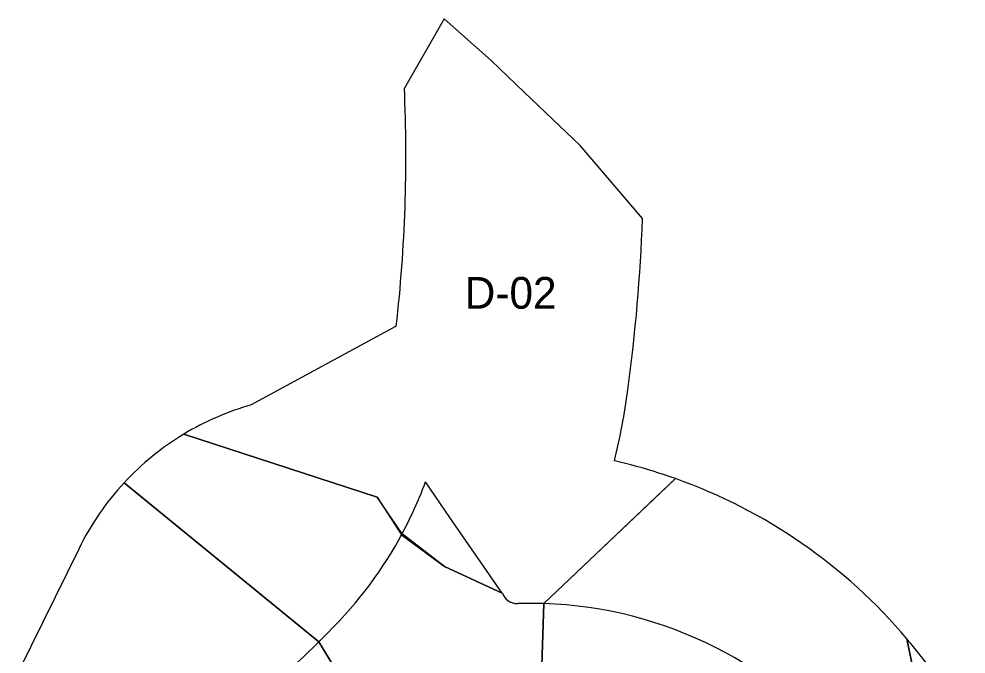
# Model space of a CAD drawing. Extents: x 5196716 to 5200291, y 3709146 to 3713154.
# Drawn here: x 5196804.5 to 5196983.8, y 3709425.2 to 3709545.4 of the extents above; entities that cross this region are included whole.
import ezdxf

# ---------------------------------------------------------------- set-up
doc = ezdxf.new("R2010")
doc.units = 0
for name, color, linetype in [('dsnTextNote', 7, 'Continuous'), ('Level 1', 7, 'Continuous'), ('Level 2', 7, 'Continuous')]:
    doc.layers.add(name, color=color, linetype=linetype)

msp = doc.modelspace()

# ---------------------------------------------------------------- linework, layer by layer
at = {"layer": 'Level 1'}
for p, q in [((5196884.99, 3709545.38), (5196877.49, 3709532.31)), ((5196922.56, 3709507.59), (5196910.77, 3709521.46)), ((5196875.95, 3709487.24), (5196848.49, 3709472.33)), ((5196920.33, 3709460.99), (5196917.26, 3709461.79)), ((5196903.91, 3709434.75), (5196928.82, 3709458.39)), ((5196928.82, 3709458.39), (5196927.19, 3709456.84)), ((5196824.43, 3709457.61), (5196838.6, 3709446.05)), ((5196927.19, 3709456.84), (5196922.24, 3709452.14)), ((5196922.24, 3709452.14), (5196903.91, 3709434.75)), ((5196922.24, 3709452.14), (5196903.91, 3709434.75)), ((5196838.6, 3709446.05), (5196861.31, 3709427.51)), ((5196815.9, 3709445.18), (5196804.52, 3709421.99)), ((5196903.91, 3709434.75), (5196902.74, 3709399.27)), ((5196902.74, 3709399.27), (5196903.91, 3709434.75)), ((5196903.91, 3709434.75), (5196902.74, 3709399.27)), ((5196874.95, 3709404.96), (5196861.31, 3709427.51)), ((5196861.31, 3709427.51), (5196874.95, 3709404.96)), ((5196993.25, 3709402.11), (5196974.62, 3709425.62))]:
    msp.add_line(p, q, dxfattribs=at)
for points in [[(5196910.77, 3709521.46), (5196900.25, 3709531.49), (5196893.9, 3709537.51), (5196884.99, 3709545.38)], [(5196877.1, 3709447.93), (5196872.32, 3709454.91), (5196835.71, 3709466.79)], [(5196835.71, 3709466.79), (5196872.32, 3709454.91), (5196876.97, 3709447.75)], [(5196928.82, 3709458.39), (5196927.19, 3709456.84), (5196922.24, 3709452.14)], [(5196861.31, 3709427.51), (5196838.6, 3709446.05), (5196824.43, 3709457.61)], [(5196876.97, 3709447.75), (5196885.1, 3709441.76), (5196896.03, 3709436.71)], [(5196896.03, 3709436.71), (5196885.1, 3709441.76), (5196877.1, 3709447.93)], [(5196898.85, 3709434.75), (5196898.94, 3709434.75)], [(5196972.61, 3709428.08), (5196978.06, 3709401.82), (5196980.89, 3709391.88), (5196981.68, 3709390)], [(5196981.68, 3709390), (5196980.89, 3709391.88), (5196978.06, 3709401.82), (5196972.61, 3709428.08)]]:
    msp.add_lwpolyline(points, dxfattribs=at)
for centre, radius, start, end in [((5196592.28, 3709519.5), 285.5, 353.512, 2.5728), ((5196592.28, 3709519.5), 330.5, 352.292, 357.936), ((5196790.47, 3709492.67), 130.5, 346.3114, 352.292), ((5196862.58, 3709422.27), 52, 105.7213, 121.1144), ((5196862.58, 3709422.27), 52, 121.1144, 137.1886), ((5196894.68, 3709362.27), 102, 70.4438, 75.4333), ((5196894.68, 3709362.27), 102, 40.1801, 70.4438), ((5196862.58, 3709422.27), 52, 137.1886, 153.8681), ((5196898.85, 3709437.75), 3, 200.28, 271.7877), ((5196898.85, 3709437.75), 3, 200.28, 270), ((5196901.36, 3709357.29), 77.5, 88.1128, 91.7877), ((5196901.36, 3709357.29), 77.5, 88.1128, 91.7877), ((5196894.68, 3709362.27), 102, 38.3928, 40.1801)]:
    msp.add_arc(centre, radius, start, end, dxfattribs=at)
at = {"layer": 'Level 2'}
for p, q in [((5196902.74, 3709399.27), (5196903.91, 3709434.75)), ((5196903.91, 3709434.75), (5196902.74, 3709399.27)), ((5196861.31, 3709427.51), (5196874.95, 3709404.96)), ((5196874.95, 3709404.96), (5196861.31, 3709427.51))]:
    msp.add_line(p, q, dxfattribs=at)
msp.add_lwpolyline([(5196896.03, 3709436.71), (5196886.07, 3709451.03), (5196881.5, 3709457.76)], dxfattribs=at)
for centre, radius, start, end in [((5196790.47, 3709492.67), 97.5, 335.3542, 339.0156), ((5196810.92, 3709483.29), 75, 317.5889, 335.3542), ((5196898.85, 3709437.75), 3, 200.28, 270), ((5196898.85, 3709437.75), 3, 270, 271.7877), ((5196901.36, 3709357.29), 77.5, 88.1128, 91.7877), ((5196901.36, 3709357.29), 77.5, 38.2026, 88.1128), ((5196755.55, 3709533.87), 150, 314.8402, 317.5889), ((5196755.55, 3709533.87), 150, 297.5187, 314.8402)]:
    msp.add_arc(centre, radius, start, end, dxfattribs=at)

# ---------------------------------------------------------------- texts
at = {"layer": 'dsnTextNote'}
msp.add_text('D-02', height=6, dxfattribs=at).set_placement((5196888.91, 3709490.55))

doc.saveas('drawing.dxf')
